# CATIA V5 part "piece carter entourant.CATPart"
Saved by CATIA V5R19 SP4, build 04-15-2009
Part number: piece carter entourant
Bounding box of the stored display mesh (mm): x 0 to 84.1, y -133.033 to 603.106, z -76.885 to 135.27
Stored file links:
  G:\EU_thinkMotion\CFAO_2010\MMS_groupe1\MMS_groupe1\A reprendre\OK\rdeneffle\piece carter entourant.CATPart
  G:\EU_thinkMotion\CFAO_2010\MMS_groupe1\MMS_groupe1\A reprendre\OK\rdeneffle\piece haute carter.CATPart
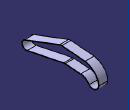
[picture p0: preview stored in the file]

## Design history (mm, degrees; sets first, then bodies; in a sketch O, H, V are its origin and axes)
Body1 (main body)
  Sketch1 on yz-plane, origin (0, 0, 0), H (0, 1, 0), V (0, 0, 1)
    line L1 (-105.7365, 5.3609) -> (240.1151, 136.1343)
    point P2 (240.1151, 136.1343)
    line L2 (-82.0775, -76.0072) -> (275.8121, -1.8097)
    arc A1 centre (-90.7051, -34.3921) radius 42.5 from (-105.7365, 5.3609) to (-82.0775, -76.0072) ccw
    line L3 (240.1151, 136.1343) -> (473.0777, 116.9639)
    point P6 (473.0777, 116.9639)
    line L4 (275.8121, -1.8097) -> (428.2967, -14.3576)
    point P7 (428.2967, -14.3576)
    point P8 (546.2195, -19.8353)
    point P9 (505.8777, -64.5809)
    point P10 (582.6766, 23.9811)
    spline S1 through (473.0777, 116.9639) (526.6966, 97.266) (583.0254, 47.3225) (603.106, -23.4317)
    spline S2 through (428.2967, -14.3576) (453.3854, -18.023) (484.1991, -35.8399) (509.4626, -63.4005)
    arc A2 centre (546.2195, -19.8353) radius 57 from (509.4626, -63.4005) to (603.106, -23.4317) ccw
    point P11 (509.4626, -63.4005)
    point P12 (603.106, -23.4317)
    line L5 (-100.4529, 2.0133) -> (241.8835, 131.4575)
    point P14 (241.8835, 131.4575)
    line L6 (-79.4126, -70.3484) -> (276.5187, 3.4431)
    arc A3 centre (-90.7051, -34.3921) radius 37.6878 from (-100.4529, 2.0133) to (-79.4126, -70.3484) ccw
    point P17 (-90.7051, -34.3921)
    line L7 (241.8835, 131.4575) -> (470.5982, 112.6366)
    point P18 (241.8835, 131.4575)
    point P19 (470.5982, 112.6366)
    line L8 (276.5187, 3.4431) -> (430.6588, -9.2411)
    point P20 (430.6588, -9.2411)
    spline S3 through (430.6588, -9.2411) (455.2823, -11.2673) (487.65, -30.3202) (511.2404, -58.3134)
    spline S4 through (470.5982, 112.6366) (526.6966, 90.417) (574.6112, 47.3225) (598.1228, -23.0216)
    arc A4 centre (546.2195, -19.8353) radius 52.001 from (511.2404, -58.3134) to (598.1228, -23.0216) ccw
    point P21 (598.1228, -23.0216)
    point P22 (511.2404, -58.3134)
    point P23 (473.0777, 116.9639)
    point P24 (603.106, -23.4317)
    point P25 (428.2967, -14.3576)
    point P28 (509.4626, -63.4005)
    point P29 (430.6588, -9.2411)
    point P30 (455.2823, -11.2673)
    point P31 (470.5982, 112.6366)
    point P32 (598.1228, -23.0216)
    point P33 (511.2404, -58.3134)
    point P34 (583.0254, 47.3225)
    point P35 (574.6112, 47.3225)
    radius A1 = 42.5
    length L2 = 365.5
    angle L1 L2 = 9
    length L1 = 369.75
    length L3 = 233.75
    length L4 = 153
    distance P8 P6 = 155.125
    distance P7 P8 = 118.05
    radius A2 = 57
    distance L5 L1 = 5
    distance L2 L6 = 5
    length L6 = 363.5
    distance P24 P32 = 5
    distance P34 P35 = 8.4141
    distance P14 P2 = 5
    distance L4 L8 = 5.2931
    distance P8 P17 = 637.091
    tangency: A1 L1, L2 A1
    parallelism: L4 L3, L2 L6, L7 L3
    coincidence: P23 P6, P25 P7, A2 P10, P24 P12, P18 P14, L8 P12, P29 P20, P30 L8, P31 P19, P32 L8, P28 P11, P32 P21, P33 P22
    concentricity: A3 A1, A4 A2
  Pad1: profile Sketch1, direction (1, 0, 0), length 84.1
  Fillet1: radius 50, on edge [face of Pad1 from Sketch1.L1 | face of Pad1 from Sketch1.L3]; edge [face of Pad1 from Sketch1.L7 | face of Pad1 from Sketch1.L5]; edge [face of Pad1 from Sketch1.L4 | face of Pad1 from Sketch1.L2]; edge [face of Pad1 from Sketch1.L6 | face of Pad1 from Sketch1.L8]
